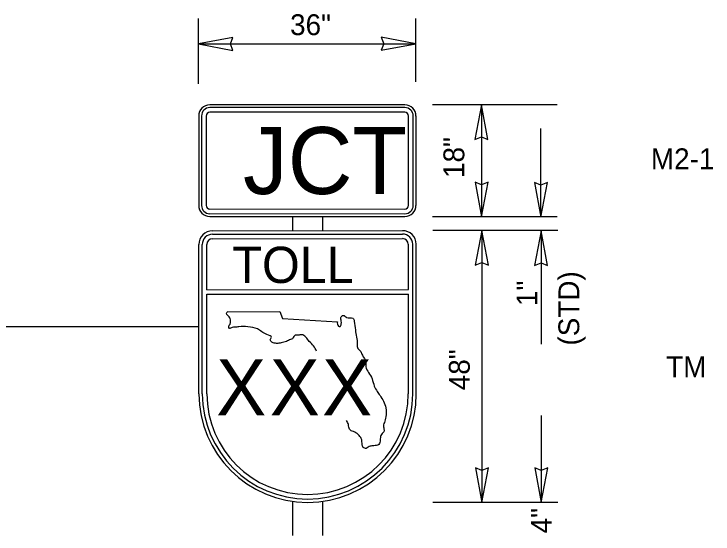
# Model space of a CAD drawing. Extents: x 52649 to 53276, y 9410 to 9783.
# Drawn here: x 52835.1 to 52923.1, y 9716.6 to 9782.1 of the extents above; entities that cross this region are included whole.
import ezdxf

# ---------------------------------------------------------------- set-up
doc = ezdxf.new("R2010")
doc.units = 0
for name, color, linetype in [('Default', 7, 'Continuous'), ('DimLines_dp', 7, 'Continuous'), ('SignPanel', 7, 'Continuous')]:
    doc.layers.add(name, color=color, linetype=linetype)

msp = doc.modelspace()

# ---------------------------------------------------------------- linework, layer by layer
at = {"layer": 'Default'}
for p, q in [((52870.202, 9754.844), (52870.202, 9756.604)), ((52873.952, 9754.846), (52873.952, 9756.602)), ((52870.201, 9716.464), (52870.203, 9720.708)), ((52873.951, 9716.464), (52873.953, 9720.71))]:
    msp.add_line(p, q, dxfattribs=at)
at = {"layer": 'DimLines_dp'}
for p, q in [((52858.305, 9773.327), (52858.305, 9781.564)), ((52885.679, 9773.579), (52885.679, 9781.564)), ((52862.655, 9779.189), (52858.305, 9778.379)), ((52862.655, 9779.189), (52858.305, 9778.379)), ((52858.305, 9778.379), (52885.679, 9778.379)), ((52858.305, 9778.379), (52862.655, 9777.539)), ((52858.305, 9778.379), (52862.655, 9777.539)), ((52862.325, 9778.379), (52862.655, 9779.189)), ((52862.325, 9778.379), (52862.655, 9779.189)), ((52862.655, 9777.539), (52862.325, 9778.379)), ((52862.655, 9777.539), (52862.325, 9778.379)), ((52885.679, 9778.379), (52881.329, 9779.219)), ((52881.329, 9779.219), (52881.659, 9778.379)), ((52881.659, 9778.379), (52881.329, 9777.569)), ((52881.329, 9777.569), (52885.679, 9778.379)), ((52903.507, 9770.675), (52887.779, 9770.675)), ((52893.961, 9770.675), (52893.121, 9766.325)), ((52894.771, 9766.325), (52893.961, 9770.675)), ((52893.961, 9770.675), (52893.961, 9756.601)), ((52901.429, 9756.561), (52901.429, 9767.729)), ((52893.121, 9766.325), (52893.961, 9766.655)), ((52893.961, 9766.655), (52894.771, 9766.325)), ((52893.961, 9760.621), (52893.151, 9760.951)), ((52893.151, 9760.951), (52893.961, 9756.601)), ((52893.961, 9756.601), (52894.801, 9760.951)), ((52894.801, 9760.951), (52893.961, 9760.621)), ((52901.429, 9760.581), (52900.619, 9760.911)), ((52900.619, 9760.911), (52901.429, 9756.561)), ((52901.429, 9756.561), (52902.269, 9760.911)), ((52902.269, 9760.911), (52901.429, 9760.581)), ((52903.507, 9756.601), (52887.779, 9756.601)), ((52903.56, 9754.851), (52887.832, 9754.851)), ((52894.014, 9754.851), (52893.174, 9750.501)), ((52894.014, 9754.851), (52893.174, 9750.501)), ((52894.014, 9754.851), (52894.014, 9720.623)), ((52894.824, 9750.501), (52894.014, 9754.851)), ((52894.824, 9750.501), (52894.014, 9754.851)), ((52901.482, 9754.811), (52900.642, 9750.461)), ((52901.482, 9754.811), (52901.482, 9740.571)), ((52902.292, 9750.461), (52901.482, 9754.811)), ((52893.174, 9750.501), (52894.014, 9750.831)), ((52893.174, 9750.501), (52894.014, 9750.831)), ((52894.014, 9750.831), (52894.824, 9750.501)), ((52894.014, 9750.831), (52894.824, 9750.501)), ((52900.642, 9750.461), (52901.482, 9750.791)), ((52901.482, 9750.791), (52902.292, 9750.461)), ((52858.36, 9742.73), (52784.107, 9742.73)), ((52901.482, 9731.585), (52901.482, 9720.623)), ((52894.014, 9724.643), (52893.204, 9724.973)), ((52893.204, 9724.973), (52894.014, 9720.623)), ((52894.014, 9724.643), (52893.204, 9724.973)), ((52893.204, 9724.973), (52894.014, 9720.623)), ((52894.014, 9720.623), (52894.854, 9724.973)), ((52894.854, 9724.973), (52894.014, 9724.643)), ((52894.014, 9720.623), (52894.854, 9724.973)), ((52894.854, 9724.973), (52894.014, 9724.643)), ((52901.482, 9724.643), (52900.672, 9724.973)), ((52900.672, 9724.973), (52901.482, 9720.623)), ((52901.482, 9724.643), (52900.672, 9724.973)), ((52900.672, 9724.973), (52901.482, 9720.623)), ((52901.482, 9720.623), (52902.322, 9724.973)), ((52902.322, 9724.973), (52901.482, 9724.643)), ((52901.482, 9720.623), (52902.322, 9724.973)), ((52902.322, 9724.973), (52901.482, 9724.643)), ((52903.56, 9720.623), (52887.832, 9720.623))]:
    msp.add_line(p, q, dxfattribs=at)
at = {"layer": 'SignPanel'}
for p, q in [((52884.299, 9770.697), (52859.745, 9770.705)), ((52884.299, 9770.349), (52859.745, 9770.357)), ((52884.299, 9769.751), (52859.745, 9769.759)), ((52858.337, 9769.293), (52858.337, 9758.031)), ((52858.697, 9769.293), (52858.697, 9758.031)), ((52859.281, 9769.293), (52859.281, 9758.031)), ((52884.767, 9758.031), (52884.767, 9769.293)), ((52885.351, 9758.031), (52885.351, 9769.293)), ((52885.711, 9758.031), (52885.711, 9769.293)), ((52859.745, 9757.577), (52884.299, 9757.569)), ((52859.745, 9756.991), (52884.299, 9756.983)), ((52859.745, 9756.631), (52884.299, 9756.623)), ((52860.074, 9754.837), (52884.016, 9754.853)), ((52860.074, 9754.407), (52884.016, 9754.423)), ((52860.074, 9753.829), (52884.016, 9753.847)), ((52858.358, 9734.293), (52858.358, 9753.121)), ((52858.786, 9734.293), (52858.786, 9753.121)), ((52859.348, 9747.411), (52859.348, 9753.121)), ((52884.742, 9747.427), (52884.742, 9753.137)), ((52885.318, 9734.311), (52885.304, 9753.137)), ((52885.748, 9734.311), (52885.732, 9753.137)), ((52859.348, 9747.411), (52884.742, 9747.427)), ((52859.348, 9746.851), (52884.742, 9746.867)), ((52859.348, 9734.293), (52859.348, 9746.851)), ((52884.758, 9734.311), (52884.742, 9746.867)), ((52861.94, 9744.607), (52868.54, 9744.673)), ((52868.54, 9744.673), (52868.884, 9743.765)), ((52868.884, 9743.765), (52875.8, 9743.369))]:
    msp.add_line(p, q, dxfattribs=at)
for centre, radius, start, end in [((52859.745, 9769.288), 1.407, 90, 180), ((52884.3, 9769.288), 1.407, 0, 90), ((52859.745, 9769.288), 1.055, 90, 180), ((52859.745, 9769.288), 0.469, 90, 180), ((52884.3, 9769.288), 1.055, 0, 90), ((52884.3, 9769.288), 0.469, 0, 90), ((52859.745, 9758.035), 1.407, 180, 270), ((52859.745, 9758.035), 1.055, 180, 270), ((52859.745, 9758.035), 0.469, 180, 270), ((52884.3, 9758.035), 1.407, 270, 360), ((52884.3, 9758.035), 1.055, 270, 360), ((52884.3, 9758.035), 0.469, 270, 360), ((52860.067, 9753.116), 1.711, 90.03983, 180.01899), ((52884.012, 9753.133), 1.711, 0.03983, 90.03983), ((52860.067, 9753.116), 1.283, 90.03983, 180.01899), ((52860.067, 9753.116), 0.713, 90.03983, 180.01899), ((52884.012, 9753.133), 1.283, 0.03983, 90.03983), ((52884.012, 9753.133), 0.713, 0.03983, 90.03983), ((52872.05, 9734.306), 13.686, 180.03983, 0.03983), ((52872.05, 9734.306), 13.258, 180.03983, 0.03983), ((52872.05, 9734.306), 12.688, 180.03983, 0.03983)]:
    msp.add_arc(centre, radius, start, end, dxfattribs=at)
for points in [[(52862.284, 9743.071), (52862.35, 9743.467), (52862.302, 9743.781), (52861.988, 9744.177), (52861.856, 9744.441), (52861.988, 9744.673)], [(52862.284, 9743.071), (52862.35, 9743.467), (52862.302, 9743.781), (52861.988, 9744.177), (52861.856, 9744.441), (52861.988, 9744.673)], [(52875.8, 9743.369), (52875.8, 9743.089), (52875.946, 9742.807), (52876.144, 9742.759), (52876.294, 9743.089), (52876.294, 9743.467), (52876.244, 9743.913), (52876.558, 9744.177), (52876.954, 9743.913), (52877.762, 9743.815), (52877.926, 9743.451), (52878.076, 9742.345), (52878.224, 9741.439), (52878.308, 9740.581), (52878.322, 9740.151), (52878.752, 9739.623), (52878.95, 9739.161), (52879.396, 9738.353), (52879.396, 9737.709), (52879.742, 9736.967), (52880.17, 9736.191), (52880.452, 9735.267), (52880.816, 9734.591), (52881.178, 9734.079), (52881.608, 9733.353), (52881.904, 9732.529), (52881.904, 9731.389), (52881.722, 9730.697), (52881.608, 9730.399), (52881.674, 9729.889), (52881.674, 9729.525), (52881.458, 9729.295), (52881.278, 9729.031), (52881.194, 9728.503), (52881.028, 9727.909), (52880.386, 9727.759), (52879.924, 9727.693), (52879.676, 9727.595), (52879.444, 9727.429), (52879.066, 9727.545), (52878.916, 9727.957), (52878.868, 9728.503), (52878.538, 9729.063), (52877.992, 9729.475), (52877.648, 9729.591), (52877.35, 9729.839), (52877.186, 9730.417), (52876.97, 9730.945)], [(52875.8, 9743.369), (52875.8, 9743.089), (52875.946, 9742.807), (52876.144, 9742.759), (52876.294, 9743.089), (52876.294, 9743.467), (52876.244, 9743.913), (52876.558, 9744.177), (52876.954, 9743.913), (52877.762, 9743.815), (52877.926, 9743.451), (52878.076, 9742.345), (52878.224, 9741.439), (52878.308, 9740.581), (52878.322, 9740.151), (52878.752, 9739.623), (52878.95, 9739.161), (52879.396, 9738.353), (52879.396, 9737.709), (52879.742, 9736.967), (52880.17, 9736.191), (52880.452, 9735.267), (52880.816, 9734.591), (52881.178, 9734.079), (52881.608, 9733.353), (52881.904, 9732.529), (52881.904, 9731.389), (52881.722, 9730.697), (52881.608, 9730.399), (52881.674, 9729.889), (52881.674, 9729.525), (52881.458, 9729.295), (52881.278, 9729.031), (52881.194, 9728.503), (52881.028, 9727.909), (52880.386, 9727.759), (52879.924, 9727.693), (52879.676, 9727.595), (52879.444, 9727.429), (52879.066, 9727.545), (52878.916, 9727.957), (52878.868, 9728.503), (52878.538, 9729.063), (52877.992, 9729.475), (52877.648, 9729.591), (52877.35, 9729.839), (52877.186, 9730.417), (52876.97, 9730.945)], [(52873.16, 9739.689), (52872.812, 9740.333), (52872.268, 9740.893), (52871.84, 9741.439), (52871.294, 9741.735), (52870.864, 9741.685), (52870.502, 9741.669), (52870.304, 9741.537), (52870.138, 9741.241), (52869.908, 9741.141), (52869.38, 9740.893), (52868.738, 9740.713), (52868.144, 9740.647), (52867.564, 9740.811), (52867.352, 9741.109), (52867.498, 9741.421), (52866.938, 9741.751), (52865.734, 9742.477), (52864.528, 9742.741), (52863.406, 9742.741), (52862.878, 9742.675), (52862.548, 9742.643), (52862.204, 9742.543), (52862.12, 9742.825), (52862.284, 9743.071)], [(52873.16, 9739.689), (52872.812, 9740.333), (52872.268, 9740.893), (52871.84, 9741.439), (52871.294, 9741.735), (52870.864, 9741.685), (52870.502, 9741.669), (52870.304, 9741.537), (52870.138, 9741.241), (52869.908, 9741.141), (52869.38, 9740.893), (52868.738, 9740.713), (52868.144, 9740.647), (52867.564, 9740.811), (52867.352, 9741.109), (52867.498, 9741.421), (52866.938, 9741.751), (52865.734, 9742.477), (52864.528, 9742.741), (52863.406, 9742.741), (52862.878, 9742.675), (52862.548, 9742.643), (52862.204, 9742.543), (52862.12, 9742.825), (52862.284, 9743.071)]]:
    msp.add_spline(points, degree=3, dxfattribs=at)

# ---------------------------------------------------------------- texts
at = {"layer": 'DimLines_dp'}
for s, p in [('36"', (52869.847, 9779.474)), ('M2-1', (52915.295, 9762.585)), ('TM', (52917.224, 9736.39))]:
    msp.add_text(s, height=2.625, dxfattribs=at).set_placement(p)
for s, p in [('18"', (52891.79, 9761.484)), ('(STD)', (52906.269, 9740.377)), ('1"', (52900.993, 9745.355)), ('48"', (52892.479, 9734.751)), ('4"', (52902.802, 9716.72))]:
    msp.add_text(s, height=2.625, rotation=90, dxfattribs=at).set_placement(p)
at = {"layer": 'SignPanel'}
msp.add_text('JCT', height=8.4386, dxfattribs=at).set_placement((52863.915, 9759.457))
for s, height, rotation, p in [('TOLL', 4.5708, 0.03983, (52862.577, 9748.25)), ('X', 7.036, 0.04985, (52860.551, 9731.602)), ('X', 7.036, 0.04985, (52867.303, 9731.602)), ('X', 7.036, 0.04985, (52873.89, 9731.602))]:
    msp.add_text(s, height=height, rotation=rotation, dxfattribs=at).set_placement(p)

doc.saveas('drawing.dxf')
